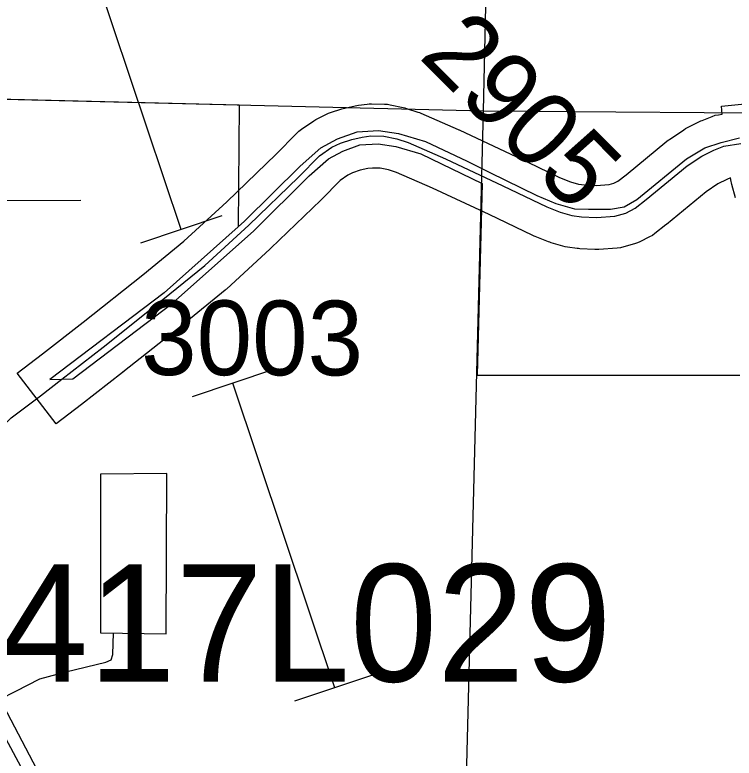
# Model space of a CAD drawing. Extents: x -157.2 to -99.3, y 12.2 to 46.2.
# Drawn here: x -146.167 to -145.492, y 30.447 to 31.144 of the extents above; entities that cross this region are included whole.
import ezdxf

# ---------------------------------------------------------------- set-up
doc = ezdxf.new("R2010")
doc.units = 0
for name, color, linetype in [('tdCoCityStreetMajor', 7, 'Continuous'), ('tdCoCityStreetMinor', 7, 'Continuous'), ('tdCoCorpBndry', 7, 'Continuous'), ('tdCoPipe', 7, 'Continuous'), ('tdCoRRCL', 7, 'Continuous'), ('tdCoSecRdNmbr', 7, 'Continuous'), ('tdCoSecRteBand', 7, 'Continuous'), ('tdCoSecRteCL', 7, 'Continuous'), ('tdCoSectLine', 7, 'Continuous'), ('tdCoStrucPriMaintName', 7, 'Continuous'), ('tdCoSurfGravel', 7, 'Continuous')]:
    doc.layers.add(name, color=color, linetype=linetype)

msp = doc.modelspace()

# ---------------------------------------------------------------- linework, layer by layer
at = {"layer": 'tdCoCityStreetMajor'}
for points in [[(-146.24512, 30.63013), (-146.24021, 30.64704), (-146.23429, 30.66233), (-146.2259, 30.68181), (-146.21456, 30.70574), (-146.2005, 30.73212), (-146.19458, 30.74075), (-146.1862, 30.75062), (-146.16992, 30.76591), (-146.14255, 30.78638), (-146.1224, 30.80219)], [(-145.98365, 30.12303), (-146.02255, 30.20026), (-146.03394, 30.22214), (-146.07566, 30.30228), (-146.10664, 30.36179), (-146.11525, 30.37809), (-146.18066, 30.50203)]]:
    msp.add_lwpolyline(points, dxfattribs=at)
at = {"layer": 'tdCoCityStreetMinor'}
msp.add_line((-146.34927, 30.96903), (-146.1046, 30.96987), dxfattribs=at)
for points in [[(-146.08111, 30.53681), (-146.07618, 30.53903), (-146.0747, 30.54396), (-146.07395, 30.56421)], [(-146.18066, 30.50203), (-146.1657, 30.50969), (-146.14301, 30.52103), (-146.11884, 30.52769), (-146.08111, 30.53681)]]:
    msp.add_lwpolyline(points, dxfattribs=at)
at = {"layer": 'tdCoCorpBndry'}
for points in [[(-146.38444, 31.06971), (-145.95609, 31.05928), (-145.95716, 30.9448), (-146.02666, 30.88293), (-146.13385, 30.80184), (-146.1224, 30.80219), (-146.11225, 30.8025), (-146.01872, 30.87326), (-145.94249, 30.94113), (-145.89049, 30.99261), (-145.87245, 31.00865), (-145.85894, 31.01589), (-145.84306, 31.02166), (-145.8259, 31.02261), (-145.80929, 31.02017), (-145.78573, 31.01316), (-145.72833, 30.9856), (-145.73289, 30.80584), (-145.48656, 30.80591)], [(-146.38444, 31.06971), (-145.95609, 31.05928), (-145.95716, 30.9448), (-145.95105, 30.95025), (-145.89905, 31.00173), (-145.87965, 31.01897), (-145.86405, 31.02733), (-145.8456, 31.03404), (-145.82533, 31.03516), (-145.80658, 31.03241), (-145.78125, 31.02486), (-145.7423, 31.00644), (-145.72091, 30.99592), (-145.67688, 30.97425), (-145.65922, 30.96668), (-145.64161, 30.96179), (-145.62842, 30.9613), (-145.60777, 30.9613), (-145.59488, 30.9636), (-145.58325, 30.97058), (-145.53647, 31.00852), (-145.51936, 31.01901), (-145.50389, 31.02398), (-145.48683, 31.02825)]]:
    msp.add_lwpolyline(points, dxfattribs=at)
msp.add_lwpolyline([(-146.08637, 30.71312), (-146.08633, 30.56441), (-146.02455, 30.5634), (-146.02387, 30.71365)], close=True, dxfattribs=at)
at = {"layer": 'tdCoPipe'}
for p, q in [((-145.97231, 30.95518), (-146.04856, 30.92958)), ((-145.92392, 30.81105), (-146.00032, 30.7854)), ((-145.82813, 30.52567), (-145.90439, 30.50007))]:
    msp.add_line(p, q, dxfattribs=at)
for points in [[(-146.0105, 30.94236), (-146.10629, 31.22773)], [(-145.86632, 30.51285), (-145.96212, 30.79823)]]:
    msp.add_lwpolyline(points, dxfattribs=at)
at = {"layer": 'tdCoRRCL'}
msp.add_lwpolyline([(-146.13896, 30.39795), (-146.19705, 30.50565), (-146.20128, 30.52158)], dxfattribs=at)
at = {"layer": 'tdCoSecRteBand'}
msp.add_lwpolyline([(-145.49063, 30.9721), (-145.49408, 30.98468), (-145.49445, 30.98603), (-145.4947, 30.98741), (-145.49527, 30.99066), (-145.49875, 30.98929), (-145.50719, 30.98507), (-145.51797, 30.97781), (-145.55534, 30.94715), (-145.55558, 30.94695), (-145.55583, 30.94676), (-145.56619, 30.93862), (-145.56859, 30.93674), (-145.57131, 30.93537), (-145.58019, 30.93093), (-145.58259, 30.92973), (-145.58518, 30.92898), (-145.59529, 30.92602), (-145.59837, 30.92511), (-145.60158, 30.92488), (-145.61884, 30.92365), (-145.62069, 30.92352), (-145.62255, 30.92362), (-145.63661, 30.92436), (-145.63783, 30.92442), (-145.63905, 30.92459), (-145.64817, 30.92582), (-145.65045, 30.92613), (-145.65266, 30.92678), (-145.66351, 30.92998), (-145.66475, 30.93035), (-145.66596, 30.93083), (-145.67854, 30.93576), (-145.67956, 30.93616), (-145.68055, 30.93663), (-145.72161, 30.9563), (-145.77485, 30.98121), (-145.80843, 30.99577), (-145.81607, 30.99826), (-145.82381, 30.99984), (-145.83106, 30.99999), (-145.83559, 30.99944), (-145.84261, 30.99786), (-145.84993, 30.99547), (-145.85424, 30.99338), (-145.86153, 30.98843), (-145.87891, 30.97061), (-145.87923, 30.97027), (-145.87957, 30.96995), (-145.92643, 30.92482), (-145.9267, 30.92456), (-145.92697, 30.9243), (-145.96815, 30.88657), (-145.96878, 30.886), (-145.96943, 30.88547), (-146.00864, 30.85341), (-146.00881, 30.85327), (-146.00898, 30.85314), (-146.0652, 30.8085), (-146.06535, 30.80838), (-146.0655, 30.80827), (-146.10404, 30.77846), (-146.12778, 30.76011), (-146.16448, 30.80757), (-146.14075, 30.82592), (-146.10236, 30.85561), (-146.04645, 30.9), (-146.00806, 30.93138), (-145.96778, 30.96829), (-145.92153, 31.01284), (-145.90238, 31.03247), (-145.90027, 31.03463), (-145.89778, 31.03633), (-145.88619, 31.04422), (-145.88438, 31.04545), (-145.8824, 31.04641), (-145.87426, 31.05036), (-145.87241, 31.05126), (-145.87046, 31.05189), (-145.85985, 31.05534), (-145.85852, 31.05578), (-145.85715, 31.05609), (-145.84729, 31.05831), (-145.84581, 31.05864), (-145.84431, 31.05882), (-145.83617, 31.05981), (-145.83407, 31.06006), (-145.83195, 31.06002), (-145.81987, 31.05977), (-145.81715, 31.05972), (-145.81448, 31.05917), (-145.8024, 31.0567), (-145.80073, 31.05636), (-145.79911, 31.05584), (-145.78851, 31.05238), (-145.78716, 31.05195), (-145.78586, 31.05138), (-145.7506, 31.03609), (-145.7502, 31.03592), (-145.74981, 31.03574), (-145.69605, 31.01059), (-145.69593, 31.01053), (-145.69581, 31.01047), (-145.65561, 30.99122), (-145.64526, 30.98716), (-145.63786, 30.98497), (-145.63223, 30.98421), (-145.62126, 30.98363), (-145.60906, 30.9845), (-145.60461, 30.9858), (-145.60087, 30.98768), (-145.59315, 30.99374), (-145.55493, 31.0251), (-145.55382, 31.02601), (-145.55264, 31.0268), (-145.53908, 31.03593), (-145.53748, 31.037), (-145.53575, 31.03787), (-145.52441, 31.04354), (-145.52323, 31.04413), (-145.522, 31.04461), (-145.51263, 31.04831), (-145.50972, 31.04946), (-145.50662, 31.04999), (-145.50301, 31.0506), (-145.50373, 31.05792), (-145.44402, 31.06377)], dxfattribs=at)
at = {"layer": 'tdCoSecRteCL'}
msp.add_lwpolyline([(-146.1224, 30.80219), (-146.08386, 30.832), (-146.02763, 30.87663), (-145.98842, 30.90869), (-145.94724, 30.94642), (-145.90038, 30.99155), (-145.8809, 31.01153), (-145.86931, 31.01942), (-145.86117, 31.02337), (-145.85057, 31.02682), (-145.8407, 31.02904), (-145.83256, 31.03002), (-145.82048, 31.02978), (-145.8084, 31.02731), (-145.79779, 31.02386), (-145.76253, 31.00857), (-145.70877, 30.98341), (-145.66759, 30.96369), (-145.65501, 30.95875), (-145.64416, 30.95555), (-145.63503, 30.95432), (-145.62098, 30.95358), (-145.60371, 30.95481), (-145.5936, 30.95777), (-145.58473, 30.96221), (-145.57437, 30.97034), (-145.5359, 31.00191), (-145.52233, 31.01103), (-145.51099, 31.01671), (-145.50162, 31.02041), (-145.48559, 31.02312)], dxfattribs=at)
at = {"layer": 'tdCoSectLine'}
for points in [[(-145.72698, 31.05369), (-145.70435, 32.06223)], [(-146.70324, 31.07747), (-145.72698, 31.05369)], [(-145.75217, 30.06052), (-145.72698, 31.05369)], [(-145.72698, 31.05369), (-144.73359, 31.04611)]]:
    msp.add_lwpolyline(points, dxfattribs=at)
at = {"layer": 'tdCoSurfGravel'}
msp.add_lwpolyline([(-146.1224, 30.80219), (-146.08386, 30.832), (-146.02763, 30.87663), (-145.98842, 30.90869), (-145.94724, 30.94642), (-145.90038, 30.99155), (-145.8809, 31.01153), (-145.86931, 31.01942), (-145.86117, 31.02337), (-145.85057, 31.02682), (-145.8407, 31.02904), (-145.83256, 31.03002), (-145.82048, 31.02978), (-145.8084, 31.02731), (-145.79779, 31.02386), (-145.76253, 31.00857), (-145.70877, 30.98341), (-145.66759, 30.96369), (-145.65501, 30.95875), (-145.64416, 30.95555), (-145.63503, 30.95432), (-145.62098, 30.95358), (-145.60371, 30.95481), (-145.5936, 30.95777), (-145.58473, 30.96221), (-145.57437, 30.97034), (-145.5359, 31.00191), (-145.52233, 31.01103), (-145.51099, 31.01671), (-145.50162, 31.02041), (-145.48559, 31.02312)], dxfattribs=at)

# ---------------------------------------------------------------- texts
at = {"layer": 'tdCoSecRdNmbr'}
for s, rotation, p in [('2905', 314.88846, (-145.7887, 31.10389)), ('3003', 359.88859, (-146.04819, 30.80598))]:
    msp.add_text(s, height=0.07, rotation=rotation, dxfattribs=at).set_placement(p)
at = {"layer": 'tdCoStrucPriMaintName'}
msp.add_text('97417L029', height=0.11, dxfattribs=at).set_placement((-146.34305, 30.51858))

doc.saveas('drawing.dxf')
